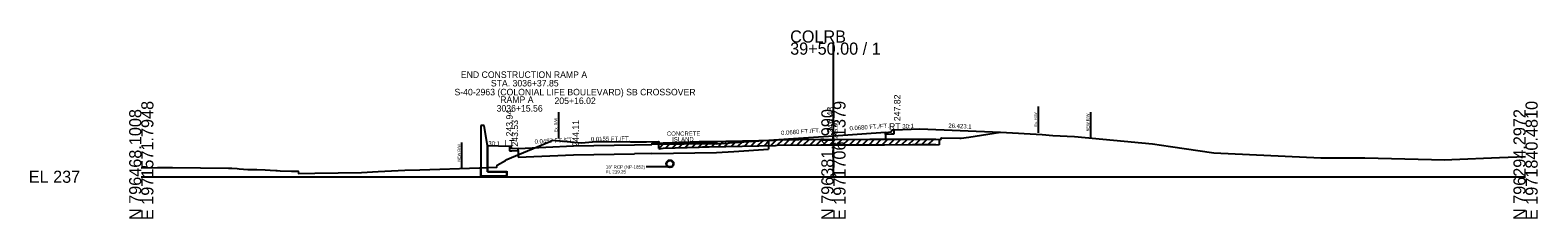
# Model space of a CAD drawing. Extents: x -26 to 1971766, y -10 to 796432.
# Drawn here: x -25.7 to 322.8, y 3990.3 to 4033.8 of the extents above; entities that cross this region are included whole.
import ezdxf

# ---------------------------------------------------------------- set-up
doc = ezdxf.new("R2010")
doc.units = 0
for name, color, linetype in [('BR_AUTO DIMENSION', 7, 'Continuous'), ('BR_BORDER LINES', 7, 'Continuous'), ('BR_CENTER LINE BASELINE', 7, 'Continuous'), ('BR_CONCRETE', 7, 'Continuous'), ('BR_DETAILS', 7, 'Continuous'), ('BR_PRESTRESSED BEAM', 7, 'Continuous'), ('BR_REBAR', 7, 'Continuous'), ('BR_TABLE LINES', 7, 'Continuous'), ('Default', 7, 'Continuous'), ('Level 31', 7, 'Continuous'), ('MISCELLANEOUS', 7, 'Continuous'), ('North Arrow', 7, 'Continuous'), ('RD_EX_Conc', 7, 'Continuous'), ('RD_EX_Road', 7, 'Continuous'), ('RD_HC_CL_Rel', 7, 'Continuous'), ('RD_PD_ALT2_TnTmp', 7, 'Continuous'), ('RD_PD_CstnLmt', 7, 'Continuous'), ('RD_PD_Final_LnLine', 7, 'Continuous'), ('RD_PD_Final_TrvlWay', 7, 'Continuous'), ('RD_PD_FOC', 7, 'Continuous'), ('RD_PD_MedBWall', 7, 'Continuous'), ('RD_PD_WallFill', 7, 'Continuous'), ('RD_SHT_IplotShp', 7, 'Continuous')]:
    doc.layers.add(name, color=color, linetype=linetype)

msp = doc.modelspace()

# ---------------------------------------------------------------- linework, layer by layer
at = {"layer": 'BR_AUTO DIMENSION'}
for p, q in [((160, 4000), (160, 4030.94)), ((0, 4000), (160, 4000)), ((160, 4000), (320, 4000))]:
    msp.add_line(p, q, dxfattribs=at)
at = {"layer": 'BR_BORDER LINES'}
msp.add_lwpolyline([(0, 4002.08), (3.77, 4002.15), (7.18, 4002.12), (20.19, 4001.99), (20.92, 4001.95), (22.14, 4001.89), (22.64, 4001.85), (24.65, 4001.7), (25.11, 4001.66), (26.31, 4001.67), (26.69, 4001.64), (28.65, 4001.57), (29.76, 4001.51), (31.12, 4001.44), (31.43, 4001.43), (32.1, 4001.37), (34.69, 4001.31), (35.22, 4001.3), (36.24, 4001.28), (36.35, 4000.78), (40.13, 4000.81), (50.88, 4000.98), (54.79, 4001.22), (60.91, 4001.55), (64.36, 4001.59), (78.18, 4002.04), (82.17, 4002.19), (82.27, 4002.69), (84.16, 4003.77), (84.51, 4003.96), (85.55, 4004.4), (94.25, 4008.06), (95.07, 4008.41), (101.76, 4007.81), (105.19, 4008.09), (105.85, 4008.1), (113.12, 4008.06), (116.81, 4008.07), (119.58, 4008.09), (119.69, 4007.69), (120.62, 4007.8), (128.98, 4008.09), (129.72, 4008.12), (131.26, 4008.15), (146.63, 4008.44), (147.01, 4008.5), (157.12, 4008.63), (157.72, 4008.63), (158.09, 4008.59), (160, 4008.6), (168.4, 4008.64), (171.83, 4008.64), (178.31, 4008.65), (183.69, 4008.67), (184.84, 4008.57), (184.95, 4008.97), (189.19, 4008.88), (189.51, 4008.87), (191.32, 4009.13), (198.59, 4010.31), (208.25, 4009.74), (210.75, 4009.51), (215.75, 4009.26), (233.77, 4007.55), (237.94, 4006.94), (247.97, 4005.48), (272.68, 4004.36), (282.87, 4004.33), (301.3, 4003.9), (302.94, 4004.01), (313.98, 4004.43), (320, 4004.7)], dxfattribs=at)
at = {"layer": 'BR_CENTER LINE BASELINE'}
for p, q in [((184.45, 4008.6), (184.45, 4007.35)), ((119.67, 4006.51), (119.67, 4007.76)), ((119.67, 4006.51), (119.69, 4006.44)), ((119.69, 4006.44), (120.62, 4006.55)), ((120.62, 4006.55), (128.98, 4006.84)), ((128.98, 4006.84), (129.72, 4006.87)), ((129.72, 4006.87), (131.26, 4006.9)), ((131.26, 4006.9), (146.63, 4007.19)), ((146.63, 4007.19), (147.01, 4007.25)), ((147.01, 4007.25), (157.12, 4007.38)), ((157.12, 4007.38), (157.72, 4007.38)), ((157.72, 4007.38), (158.09, 4007.34)), ((158.09, 4007.34), (160, 4007.35)), ((160, 4007.35), (168.4, 4007.39)), ((168.4, 4007.39), (171.83, 4007.39)), ((171.83, 4007.39), (178.31, 4007.4)), ((178.31, 4007.4), (183.69, 4007.42)), ((183.69, 4007.42), (184.45, 4007.35))]:
    msp.add_line(p, q, dxfattribs=at)
at = {"layer": 'BR_DETAILS'}
for p, q in [((79.27, 4011.78), (78.52, 4011.78)), ((78.52, 4011.78), (78.52, 4000.1)), ((80.02, 4007.11), (79.27, 4011.78)), ((80.02, 4001.11), (80.02, 4007.11)), ((117.99, 4007.73), (133, 4007.95)), ((117.99, 4007.73), (117.99, 4007.4)), ((133, 4007.62), (117.99, 4007.4)), ((133, 4007.95), (133, 4007.62)), ((78.52, 4000.1), (80.02, 4000.1)), ((84.52, 4001.11), (80.02, 4001.11)), ((80.02, 4000.1), (84.52, 4000.11)), ((84.52, 4000.11), (84.52, 4001.11))]:
    msp.add_line(p, q, dxfattribs=at)
at = {"layer": 'BR_PRESTRESSED BEAM'}
for p, q in [((173.42, 4009.82), (172, 4009.72)), ((174, 4009.82), (173.42, 4009.82)), ((174, 4010.82), (174, 4009.82)), ((85.09, 4006.94), (85.09, 4005.94)), ((85.09, 4006.94), (85.09, 4005.94)), ((85.09, 4005.94), (85.68, 4005.94)), ((85.68, 4005.94), (87.1, 4006.03))]:
    msp.add_line(p, q, dxfattribs=at)
at = {"layer": 'BR_TABLE LINES'}
for p, q in [((207.31, 4016.16), (207.31, 4010.16)), ((96.42, 4014.91), (96.42, 4008.91))]:
    msp.add_line(p, q, dxfattribs=at)
at = {"layer": 'Level 31'}
for p, q in [((130.3, 4006.88), (131.59, 4008.15)), ((131.82, 4006.91), (133.11, 4008.18)), ((133.33, 4006.93), (134.62, 4008.21)), ((134.85, 4006.96), (136.14, 4008.24)), ((136.37, 4006.99), (137.66, 4008.27)), ((137.89, 4007.02), (139.18, 4008.29)), ((139.41, 4007.05), (140.7, 4008.32)), ((140.93, 4007.08), (142.22, 4008.35)), ((142.44, 4007.11), (143.73, 4008.38)), ((143.96, 4007.13), (145.25, 4008.41)), ((145.48, 4007.16), (146.8, 4008.46)), ((147, 4007.25), (148.28, 4008.51)), ((148.52, 4007.27), (149.8, 4008.53)), ((150.04, 4007.29), (151.32, 4008.55)), ((151.55, 4007.31), (152.84, 4008.57)), ((153.07, 4007.32), (154.36, 4008.59)), ((154.59, 4007.34), (155.87, 4008.61)), ((156.11, 4007.36), (157.39, 4008.63)), ((157.63, 4007.38), (158.86, 4008.6)), ((159.15, 4007.35), (160.42, 4008.6)), ((160.67, 4007.35), (161.94, 4008.61)), ((162.18, 4007.36), (163.45, 4008.62)), ((163.7, 4007.37), (164.97, 4008.62)), ((165.22, 4007.37), (166.49, 4008.63)), ((166.74, 4007.38), (168.01, 4008.64)), ((168.26, 4007.39), (169.53, 4008.64)), ((169.78, 4007.39), (171.04, 4008.64)), ((171.29, 4007.39), (172.56, 4008.64)), ((172.81, 4007.39), (174.08, 4008.65)), ((174.33, 4007.4), (175.6, 4008.65)), ((175.85, 4007.4), (177.12, 4008.65)), ((177.37, 4007.4), (178.64, 4008.65)), ((178.89, 4007.4), (180.16, 4008.66)), ((180.41, 4007.41), (181.67, 4008.66)), ((181.92, 4007.41), (183.19, 4008.67)), ((119.67, 4006.51), (120.98, 4007.81)), ((121.19, 4006.57), (122.5, 4007.86)), ((122.7, 4006.62), (124.02, 4007.92)), ((124.22, 4006.67), (125.53, 4007.97)), ((125.74, 4006.73), (127.05, 4008.02)), ((127.26, 4006.78), (128.57, 4008.08)), ((128.78, 4006.83), (130.08, 4008.12))]:
    msp.add_line(p, q, dxfattribs=at)
at = {"layer": 'MISCELLANEOUS'}
for p, q in [((129.72, 4008.12), (131.26, 4008.15)), ((131.26, 4008.15), (146.63, 4008.44)), ((146.63, 4008.44), (147.01, 4008.5)), ((147.01, 4008.5), (157.12, 4008.63)), ((157.12, 4008.63), (157.72, 4008.63)), ((157.72, 4008.63), (158.09, 4008.59)), ((158.09, 4008.59), (160, 4008.6)), ((160, 4008.6), (168.4, 4008.64)), ((168.4, 4008.64), (172, 4008.64)), ((119.67, 4007.76), (119.69, 4007.69)), ((119.69, 4007.69), (120.62, 4007.8)), ((120.62, 4007.8), (128.98, 4008.09)), ((128.98, 4008.09), (129.72, 4008.12))]:
    msp.add_line(p, q, dxfattribs=at)
at = {"layer": 'North Arrow'}
for p, q in [((137, 4007.86), (160, 4009.43)), ((160, 4009.43), (172, 4010.24)), ((87.1, 4006.53), (99.92, 4007.11)), ((99.92, 4007.11), (113.99, 4007.33))]:
    msp.add_line(p, q, dxfattribs=at)
at = {"layer": 'RD_EX_Conc'}
for p, q in [((172, 4010.22), (173.42, 4010.32)), ((172, 4010.24), (172, 4010.22)), ((173.42, 4010.32), (173.5, 4010.82)), ((173.5, 4010.82), (174, 4010.82)), ((85.59, 4006.94), (85.09, 4006.94)), ((85.59, 4006.94), (85.09, 4006.94)), ((85.68, 4006.45), (85.59, 4006.94)), ((85.68, 4006.45), (85.59, 4006.94)), ((87.1, 4006.53), (85.68, 4006.45)), ((87.1, 4006.55), (87.1, 4006.53))]:
    msp.add_line(p, q, dxfattribs=at)
at = {"layer": 'RD_EX_Road'}
for p, q in [((144.96, 4008.4), (144.96, 4006.36)), ((172, 4010.22), (172, 4010.24)), ((172, 4009.72), (172, 4010.22)), ((172, 4009.72), (172, 4008.64)), ((87.1, 4006.53), (87.1, 4006.55)), ((87.1, 4006.03), (87.1, 4006.53)), ((87.1, 4006.03), (87.1, 4004.49)), ((87.1, 4004.49), (99.93, 4005.07)), ((99.93, 4005.07), (113.99, 4005.29)), ((117.99, 4005.36), (113.99, 4005.29)), ((117.99, 4005.36), (133, 4005.58)), ((133, 4005.58), (137, 4005.82)), ((137, 4005.82), (144.96, 4006.36))]:
    msp.add_line(p, q, dxfattribs=at)
at = {"layer": 'RD_PD_CstnLmt'}
for p, q in [((219.41, 4014.91), (219.41, 4008.91)), ((74.02, 4007.9), (74.02, 4001.9))]:
    msp.add_line(p, q, dxfattribs=at)
at = {"layer": 'RD_PD_Final_LnLine'}
for p, q in [((174, 4010.82), (180, 4011.02)), ((180, 4011.02), (198.59, 4010.31)), ((80.02, 4007.11), (80.02, 4001.11)), ((78.52, 4000.1), (78.52, 4002.05)), ((84.52, 4001.26), (84.52, 4000.26)), ((80.02, 4000.1), (78.52, 4000.1)), ((80.02, 4001.11), (84.52, 4001.09)), ((84.52, 4000.11), (80.02, 4000.1))]:
    msp.add_line(p, q, dxfattribs=at)
at = {"layer": 'RD_PD_FOC'}
msp.add_line((121.71, 4002.25), (116.71, 4002.25), dxfattribs=at)
for radius in [0.85, 0.75]:
    msp.add_circle((122.21, 4003), radius, dxfattribs=at)
at = {"layer": 'RD_PD_MedBWall'}
for p, q in [((85.09, 4006.94), (80.02, 4007.11)), ((113.99, 4007.33), (117.99, 4007.4)), ((133, 4007.62), (137, 4007.86))]:
    msp.add_line(p, q, dxfattribs=at)

# ---------------------------------------------------------------- texts
at = {"layer": 'BR_AUTO DIMENSION'}
for s, p in [('COLRB', (150, 4030.94)), ('39+50.00 / 1', (150, 4028.14)), ('EL 237', (-26, 3998.6))]:
    msp.add_text(s, height=2.8, dxfattribs=at).set_placement(p)
for s, p in [('N 796468.1008', (0, 3990)), ('E 1971571.7948', (2.8, 3990)), ('N 796381.1990', (160, 3990)), ('E 1971706.1379', (162.8, 3990)), ('N 796294.2972', (320, 3990)), ('E 1971840.4810', (322.8, 3990))]:
    msp.add_text(s, height=2.8, rotation=90, dxfattribs=at).set_placement(p)
at = {"layer": 'BR_CONCRETE'}
for s, rotation, p in [('0.0680 FT./FT.', 3.8901, (163.75, 4010.68)), ('30:1', 1.9092, (175.94, 4011.13)), ('26.423:1', 357.8326, (186.55, 4011.29)), ('30:1', 358.8542, (80.21, 4007.22)), ('0.0457 FT./FT.', 2.9034, (90.94, 4007.59)), ('0.0155 FT./FT.', 0.8908, (103.93, 4008.17)), ('0.0680 FT./FT.', 3.8901, (147.93, 4009.61))]:
    msp.add_text(s, height=1, rotation=rotation, dxfattribs=at).set_placement(p)
at = {"layer": 'BR_REBAR'}
for s, p in [('RT', (172.85, 4010.82)), ('LT', (83.9, 4006.94))]:
    msp.add_text(s, height=1.5, dxfattribs=at).set_placement(p)
at = {"layer": 'BR_TABLE LINES'}
for p in [(96.17, 4010.29), (207.06, 4011.55)]:
    msp.add_text('Ex. R/W ', height=0.65, rotation=90, dxfattribs=at).set_placement(p)
at = {"layer": 'Default'}
msp.add_text('243.94', height=1.5, rotation=90, dxfattribs=at).set_placement((85.84, 4009.29))
at = {"layer": 'RD_HC_CL_Rel'}
for s, p in [(' 246.43', (160, 4009.43)), (' 243.53', (87.1, 4006.39)), (' 244.11', (101.16, 4006.39))]:
    msp.add_text(s, height=1.5, rotation=90, dxfattribs=at).set_placement(p)
at = {"layer": 'RD_PD_ALT2_TnTmp'}
for s, height, p in [('END CONSTRUCTION RAMP A', 1.5, (73.87, 4022.79)), ('STA. 3036+37.85', 1.5, (80.81, 4020.82)), ('CONCRETE', 0.999, (121.5, 4009.44)), ('ISLAND', 0.999, (122.72, 4008.13))]:
    msp.add_text(s, height=height, dxfattribs=at).set_placement(p)
at = {"layer": 'RD_PD_CstnLmt'}
for p in [(219.14, 4010.47), (73.76, 4003.46)]:
    msp.add_text('NEW R/W ', height=0.65, rotation=90, dxfattribs=at).set_placement(p)
at = {"layer": 'RD_PD_Final_TrvlWay'}
msp.add_text('247.82', height=1.5, rotation=90, dxfattribs=at).set_placement((175.5, 4012.82))
at = {"layer": 'RD_PD_FOC'}
for s, p in [('18" RCP (NP-1852)', (107.38, 4001.87)), ('FL 239.25', (107.38, 4000.75))]:
    msp.add_text(s, height=0.75, dxfattribs=at).set_placement(p)
at = {"layer": 'RD_PD_WallFill'}
for s, p in [('S-40-2963 (COLONIAL LIFE BOULEVARD) SB CROSSOVER', (72.4, 4018.77)), ('3036+15.56', (82.14, 4015.02)), ('RAMP A', (82.98, 4017.02)), ('205+16.02', (95.52, 4016.77))]:
    msp.add_text(s, height=1.5, dxfattribs=at).set_placement(p)
at = {"layer": 'RD_SHT_IplotShp'}
msp.add_text('245.60', height=1, rotation=90, dxfattribs=at).set_placement((161, 4008.75))

doc.saveas('drawing.dxf')
